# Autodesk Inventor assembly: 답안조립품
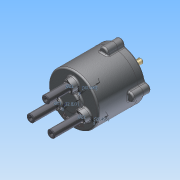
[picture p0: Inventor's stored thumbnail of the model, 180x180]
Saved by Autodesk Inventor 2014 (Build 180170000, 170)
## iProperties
Created: 2015-09
Part Number: 답안조립품
Document SubType Name: Assembly
Designer: study
Mass: 2160.27 g
Surface Area: 1801.22 cm^2
Volume: 438.525 cm^3
Density: 4.92621 g/cm^3
Author: study
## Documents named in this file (14)
- C:\Users\study\Desktop\350916V1020\답안조립품.iam
- C:\Users\study\Desktop\350916V1020\몸체.ipt
- C:\Users\study\Desktop\350916V1020\M5x0.8x20.ipt
- C:\Users\study\Desktop\350916V1020\오일실.ipt
- C:\Users\study\Desktop\350916V1020\커버.ipt
- C:\Users\study\Desktop\350916V1020\멈춤링 22 x 1.2.ipt
- C:\Users\study\Desktop\350916V1020\메인 축.ipt
- C:\Users\study\Desktop\350916V1020\베어링 NA 4900.ipt
- C:\Users\study\Desktop\350916V1020\멈춤링 10 x 1.ipt
- C:\Users\study\Desktop\350916V1020\슬라이드 축.ipt
- C:\Users\study\Desktop\350916V1020\판캠.ipt
- C:\Users\study\Desktop\350916V1020\11-가변스프링.ipt
- C:\Users\study\Desktop\350916V1020\12-가변스프링.ipt
- C:\Users\study\Desktop\350916V1020\13-가변스프링.ipt
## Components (7 placed, 4 different names)
1. 11-가변스프링:1
2. 12-가변스프링:1
3. 13-가변스프링:1
4. M5x0.8x20:1
5. M5x0.8x20:2
6. M5x0.8x20:3
7. M5x0.8x20:4
